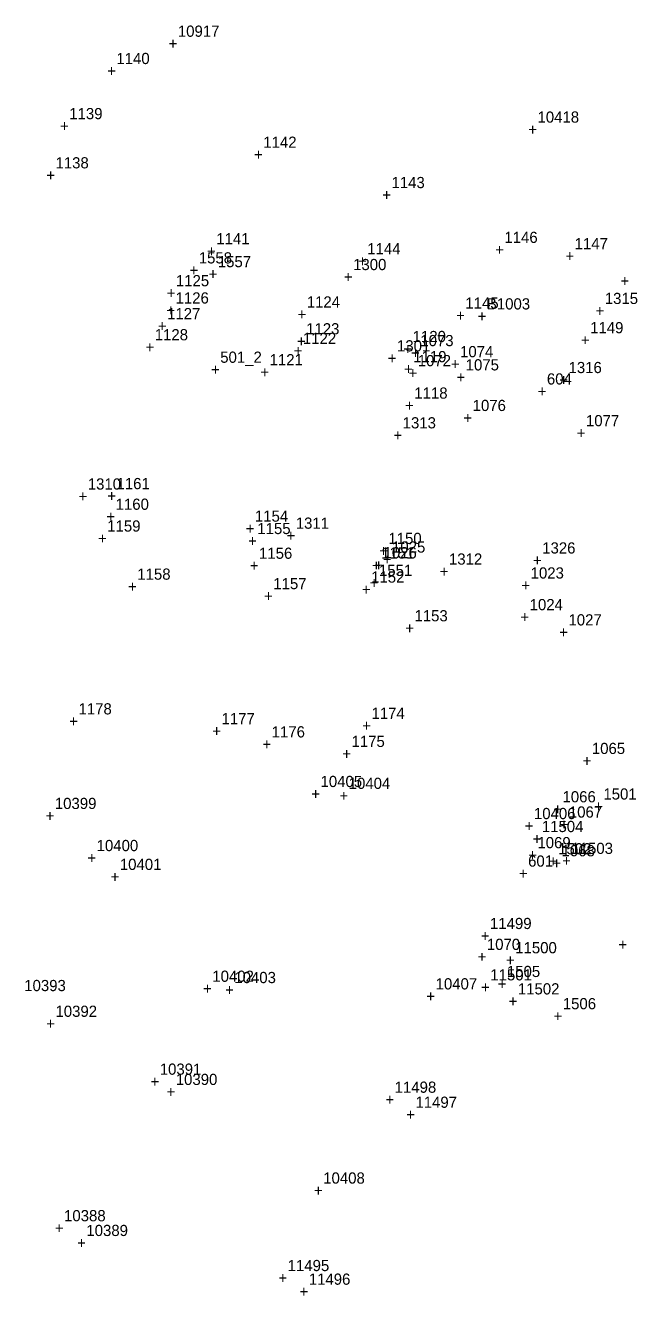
# Model space of a CAD drawing. Extents: x 1160051 to 1162814, y 614604 to 619560.
# Drawn here: x 1161295.2 to 1161430, y 617089.1 to 617372.9 of the extents above; entities that cross this region are included whole.
import ezdxf

# ---------------------------------------------------------------- set-up
doc = ezdxf.new("R2010")
doc.units = 0
for name, color, linetype in [('S_Control_Temp_Traverse', 7, 'Continuous'), ('S_Control_Traverse_Point', 7, 'Continuous'), ('S_Fencing_Page', 7, 'Continuous'), ('S_Ground_Elevation', 7, 'Continuous'), ('S_Guardrail_Beam', 7, 'Continuous'), ('S_Roadway_Edge_Shoulder', 7, 'Continuous'), ('S_Traffic_Sign_DoublePost', 7, 'Continuous'), ('S_Trees_TreeLine', 7, 'Continuous'), ('S_Utilities_UG_BoringLocation', 7, 'Continuous'), ('S_Utilities_UG_Gas_Line', 7, 'Continuous'), ('S_Utilities_UG_Sanitary_Sewer', 7, 'Continuous')]:
    doc.layers.add(name, color=color, linetype=linetype)

msp = doc.modelspace()

# ---------------------------------------------------------------- texts
at = {"layer": 'S_Control_Temp_Traverse'}
for s, p in [('604', (1161411.77, 617292.67)), ('604', (1161411.77, 617292.67)), ('+', (1161409.71, 617289.92)), ('+', (1161409.71, 617289.92)), ('601', (1161407.57, 617184.95)), ('601', (1161407.57, 617184.95)), ('601', (1161407.57, 617184.95)), ('+', (1161405.51, 617182.2)), ('+', (1161405.51, 617182.2)), ('+', (1161405.51, 617182.2))]:
    msp.add_text(s, height=2.5, dxfattribs=at).set_placement(p)
at = {"layer": 'S_Control_Traverse_Point'}
for s, p in [('501', (1161338.75, 617297.53)), ('501', (1161338.75, 617297.53)), ('501', (1161338.75, 617297.53)), ('501', (1161338.75, 617297.53)), ('501', (1161338.75, 617297.53)), ('501', (1161338.75, 617297.53)), ('501', (1161338.75, 617297.53)), ('501', (1161338.75, 617297.53)), ('501_2', (1161338.75, 617297.53)), ('+', (1161336.69, 617294.78)), ('+', (1161336.69, 617294.78)), ('+', (1161336.69, 617294.78)), ('+', (1161336.69, 617294.78)), ('+', (1161336.69, 617294.78)), ('+', (1161336.69, 617294.78)), ('+', (1161336.69, 617294.78)), ('+', (1161336.69, 617294.78)), ('+', (1161336.69, 617294.78))]:
    msp.add_text(s, height=2.5, dxfattribs=at).set_placement(p)
at = {"layer": 'S_Fencing_Page'}
for s, p in [('1067', (1161416.68, 617195.91)), ('+', (1161414.61, 617193.16))]:
    msp.add_text(s, height=2.5, dxfattribs=at).set_placement(p)
at = {"layer": 'S_Ground_Elevation'}
for s, p in [('10917', (1161329.28, 617370.37)), ('+', (1161327.22, 617367.62)), ('1140', (1161315.54, 617364.27)), ('+', (1161313.48, 617361.52)), ('1139', (1161305, 617351.95)), ('10418', (1161409.67, 617351.18)), ('+', (1161302.94, 617349.2)), ('+', (1161407.61, 617348.43)), ('1142', (1161348.37, 617345.56)), ('+', (1161346.31, 617342.81)), ('1138', (1161301.93, 617340.96)), ('+', (1161299.87, 617338.21)), ('1143', (1161377.03, 617336.55)), ('+', (1161374.97, 617333.8)), ('1146', (1161402.27, 617324.31)), ('1141', (1161337.87, 617324)), ('1144', (1161371.61, 617321.76)), ('1147', (1161417.98, 617322.91)), ('+', (1161335.81, 617321.25)), ('+', (1161369.55, 617319.01)), ('+', (1161400.21, 617321.56)), ('+', (1161415.92, 617320.16)), ('1125', (1161328.84, 617314.63)), ('+', (1161428.22, 617314.58)), ('+', (1161326.78, 617311.88)), ('1126', (1161328.77, 617310.77)), ('+', (1161326.71, 617308.02)), ('1127', (1161326.87, 617307.26)), ('1124', (1161358.09, 617309.87)), ('1145', (1161393.54, 617309.62)), ('+', (1161356.03, 617307.12)), ('+', (1161391.48, 617306.87)), ('+', (1161324.81, 617304.51)), ('1122', (1161357.23, 617301.74)), ('1123', (1161357.96, 617303.88)), ('1120', (1161381.76, 617302.15)), ('1149', (1161421.43, 617304.12)), ('+', (1161355.9, 617301.13)), ('+', (1161379.7, 617299.4)), ('1073', (1161383.47, 617301.24)), ('1074', (1161392.36, 617298.77)), ('+', (1161419.37, 617301.37)), ('+', (1161355.17, 617298.99)), ('+', (1161381.41, 617298.49)), ('1119', (1161381.89, 617297.65)), ('1072', (1161382.9, 617296.76)), ('1075', (1161393.61, 617295.82)), ('+', (1161379.83, 617294.9)), ('+', (1161380.84, 617294.01)), ('+', (1161390.3, 617296.02)), ('+', (1161391.55, 617293.07)), ('1160', (1161315.37, 617264.68)), ('+', (1161313.31, 617261.93)), ('1159', (1161313.49, 617259.81)), ('1155', (1161347.04, 617259.25)), ('+', (1161311.43, 617257.06)), ('+', (1161344.98, 617256.5)), ('1156', (1161347.42, 617253.73)), ('1151', (1161374.72, 617253.78)), ('1026', (1161375.25, 617253.84)), ('+', (1161345.36, 617250.98)), ('+', (1161372.66, 617251.03)), ('+', (1161373.19, 617251.09)), ('1158', (1161320.21, 617249.06)), ('1152', (1161372.48, 617248.4)), ('+', (1161318.15, 617246.31)), ('1157', (1161350.61, 617246.94)), ('+', (1161370.42, 617245.65)), ('+', (1161348.55, 617244.19)), ('1024', (1161407.91, 617242.25)), ('1153', (1161382.17, 617239.76)), ('+', (1161405.85, 617239.5)), ('+', (1161380.11, 617237.01)), ('1027', (1161416.59, 617238.84)), ('+', (1161414.53, 617236.09)), ('1178', (1161307.07, 617218.96)), ('1177', (1161339.04, 617216.78)), ('1174', (1161372.55, 617217.97)), ('+', (1161305, 617216.21)), ('+', (1161336.98, 617214.03)), ('1176', (1161350.25, 617213.82)), ('+', (1161370.48, 617215.22)), ('+', (1161348.19, 617211.07)), ('1175', (1161368.1, 617211.69)), ('+', (1161366.03, 617208.94)), ('1065', (1161421.82, 617210.12)), ('+', (1161419.76, 617207.37)), ('10405', (1161361.17, 617202.74)), ('+', (1161359.11, 617199.99)), ('1066', (1161415.26, 617199.32)), ('1501', (1161424.4, 617199.94)), ('10399', (1161301.78, 617197.83)), ('+', (1161422.34, 617197.19)), ('+', (1161299.72, 617195.08)), ('+', (1161413.2, 617196.57)), ('11504', (1161410.64, 617192.67)), ('10400', (1161311.12, 617188.42)), ('+', (1161408.58, 617189.92)), ('1069', (1161409.65, 617189.07)), ('+', (1161309.06, 617185.67)), ('+', (1161407.59, 617186.32)), ('1502', (1161414.28, 617187.7)), ('1068', (1161415.05, 617187.26)), ('11503', (1161417.24, 617187.79)), ('10401', (1161316.31, 617184.21)), ('+', (1161412.22, 617184.95)), ('+', (1161412.98, 617184.51)), ('+', (1161415.18, 617185.04)), ('+', (1161314.25, 617181.46)), ('11499', (1161399.05, 617171.01)), ('+', (1161396.99, 617168.26)), ('1070', (1161398.35, 617166.34)), ('11500', (1161404.69, 617165.59)), ('+', (1161427.74, 617166.31)), ('+', (1161396.29, 617163.59)), ('+', (1161402.62, 617162.84)), ('1505', (1161402.83, 617160.29)), ('10393', (1161294.94, 617157.14)), ('10402', (1161336.98, 617159.22)), ('+', (1161400.77, 617157.54)), ('+', (1161334.92, 617156.47)), ('10392', (1161301.92, 617151.39)), ('1506', (1161415.32, 617153.09)), ('+', (1161299.86, 617148.64)), ('+', (1161413.25, 617150.34)), ('10391', (1161325.23, 617138.46)), ('+', (1161323.17, 617135.71)), ('11498', (1161377.74, 617134.43)), ('+', (1161375.68, 617131.68)), ('11497', (1161382.38, 617131.07)), ('+', (1161380.32, 617128.32)), ('10388', (1161303.84, 617105.72)), ('+', (1161301.78, 617102.97)), ('11495', (1161353.82, 617094.58)), ('11496', (1161358.54, 617091.54)), ('+', (1161351.76, 617091.83)), ('+', (1161356.48, 617088.79))]:
    msp.add_text(s, height=2.5, dxfattribs=at).set_placement(p)
at = {"layer": 'S_Guardrail_Beam'}
for s, p in [('10404', (1161367.46, 617202.32)), ('+', (1161365.4, 617199.57)), ('10406', (1161408.87, 617195.57)), ('+', (1161406.81, 617192.82)), ('10403', (1161341.9, 617158.93)), ('10407', (1161386.89, 617157.52)), ('+', (1161339.84, 617156.18)), ('+', (1161384.82, 617154.77)), ('10390', (1161328.81, 617136.17)), ('+', (1161326.75, 617133.42)), ('10408', (1161361.77, 617114.13)), ('+', (1161359.71, 617111.38)), ('10389', (1161308.83, 617102.42)), ('+', (1161306.77, 617099.67))]:
    msp.add_text(s, height=2.5, dxfattribs=at).set_placement(p)
at = {"layer": 'S_Roadway_Edge_Shoulder'}
for s, p in [('1128', (1161324.11, 617302.55)), ('+', (1161322.05, 617299.8)), ('1121', (1161349.78, 617296.96)), ('+', (1161347.72, 617294.21)), ('1118', (1161382.13, 617289.51)), ('+', (1161380.07, 617286.76)), ('1076', (1161395.17, 617286.75)), ('+', (1161393.11, 617284)), ('1077', (1161420.5, 617283.35)), ('+', (1161418.44, 617280.6)), ('1161', (1161315.57, 617269.29)), ('+', (1161313.51, 617266.54)), ('1154', (1161346.5, 617262.02)), ('+', (1161344.44, 617259.27)), ('1150', (1161376.34, 617257.05)), ('+', (1161374.28, 617254.3)), ('1025', (1161377.15, 617255.12)), ('+', (1161375.09, 617252.37)), ('1023', (1161408.13, 617249.32)), ('+', (1161406.07, 617246.57))]:
    msp.add_text(s, height=2.5, dxfattribs=at).set_placement(p)
at = {"layer": 'S_Traffic_Sign_DoublePost'}
for s, p in [('11501', (1161399.12, 617159.54)), ('+', (1161397.06, 617156.79)), ('11502', (1161405.28, 617156.4)), ('+', (1161403.22, 617153.65))]:
    msp.add_text(s, height=2.5, dxfattribs=at).set_placement(p)
at = {"layer": 'S_Trees_TreeLine'}
for s, p in [('1300', (1161368.45, 617318.23)), ('+', (1161366.39, 617315.48)), ('1315', (1161424.71, 617310.66)), ('+', (1161422.65, 617307.91)), ('1301', (1161378.26, 617300.07)), ('+', (1161376.19, 617297.32)), ('1316', (1161416.61, 617295.22)), ('+', (1161414.54, 617292.47)), ('1310', (1161309.14, 617269.2)), ('+', (1161307.08, 617266.45)), ('1311', (1161355.63, 617260.45)), ('+', (1161353.57, 617257.7)), ('1312', (1161389.88, 617252.43)), ('+', (1161387.82, 617249.68))]:
    msp.add_text(s, height=2.5, dxfattribs=at).set_placement(p)
at = {"layer": 'S_Utilities_UG_BoringLocation'}
for s, p in [('1558', (1161333.95, 617319.72)), ('1557', (1161338.21, 617318.88)), ('+', (1161331.89, 617316.97)), ('+', (1161336.15, 617316.13)), ('B1003', (1161398.35, 617309.44)), ('+', (1161396.28, 617306.69)), ('1551', (1161374.23, 617249.9)), ('+', (1161372.17, 617247.15))]:
    msp.add_text(s, height=2.5, dxfattribs=at).set_placement(p)
at = {"layer": 'S_Utilities_UG_Gas_Line'}
for s, p in [('1313', (1161379.53, 617282.87)), ('+', (1161377.47, 617280.12))]:
    msp.add_text(s, height=2.5, dxfattribs=at).set_placement(p)
at = {"layer": 'S_Utilities_UG_Sanitary_Sewer'}
for s, p in [('1326', (1161410.72, 617254.91)), ('+', (1161408.66, 617252.16))]:
    msp.add_text(s, height=2.5, dxfattribs=at).set_placement(p)

doc.saveas('drawing.dxf')
